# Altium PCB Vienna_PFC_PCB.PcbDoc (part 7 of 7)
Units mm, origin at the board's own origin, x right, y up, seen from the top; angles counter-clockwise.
Board outline 447.04 x 302.51 mm, 6 copper layers (Top Layer, Signal Layer 1, Signal Layer 2, Signal Layer 3, Signal Layer 4, Bottom Layer), stack 1.231 mm thick; 630 components, 255 nets, 1656 pads, 941 vias.
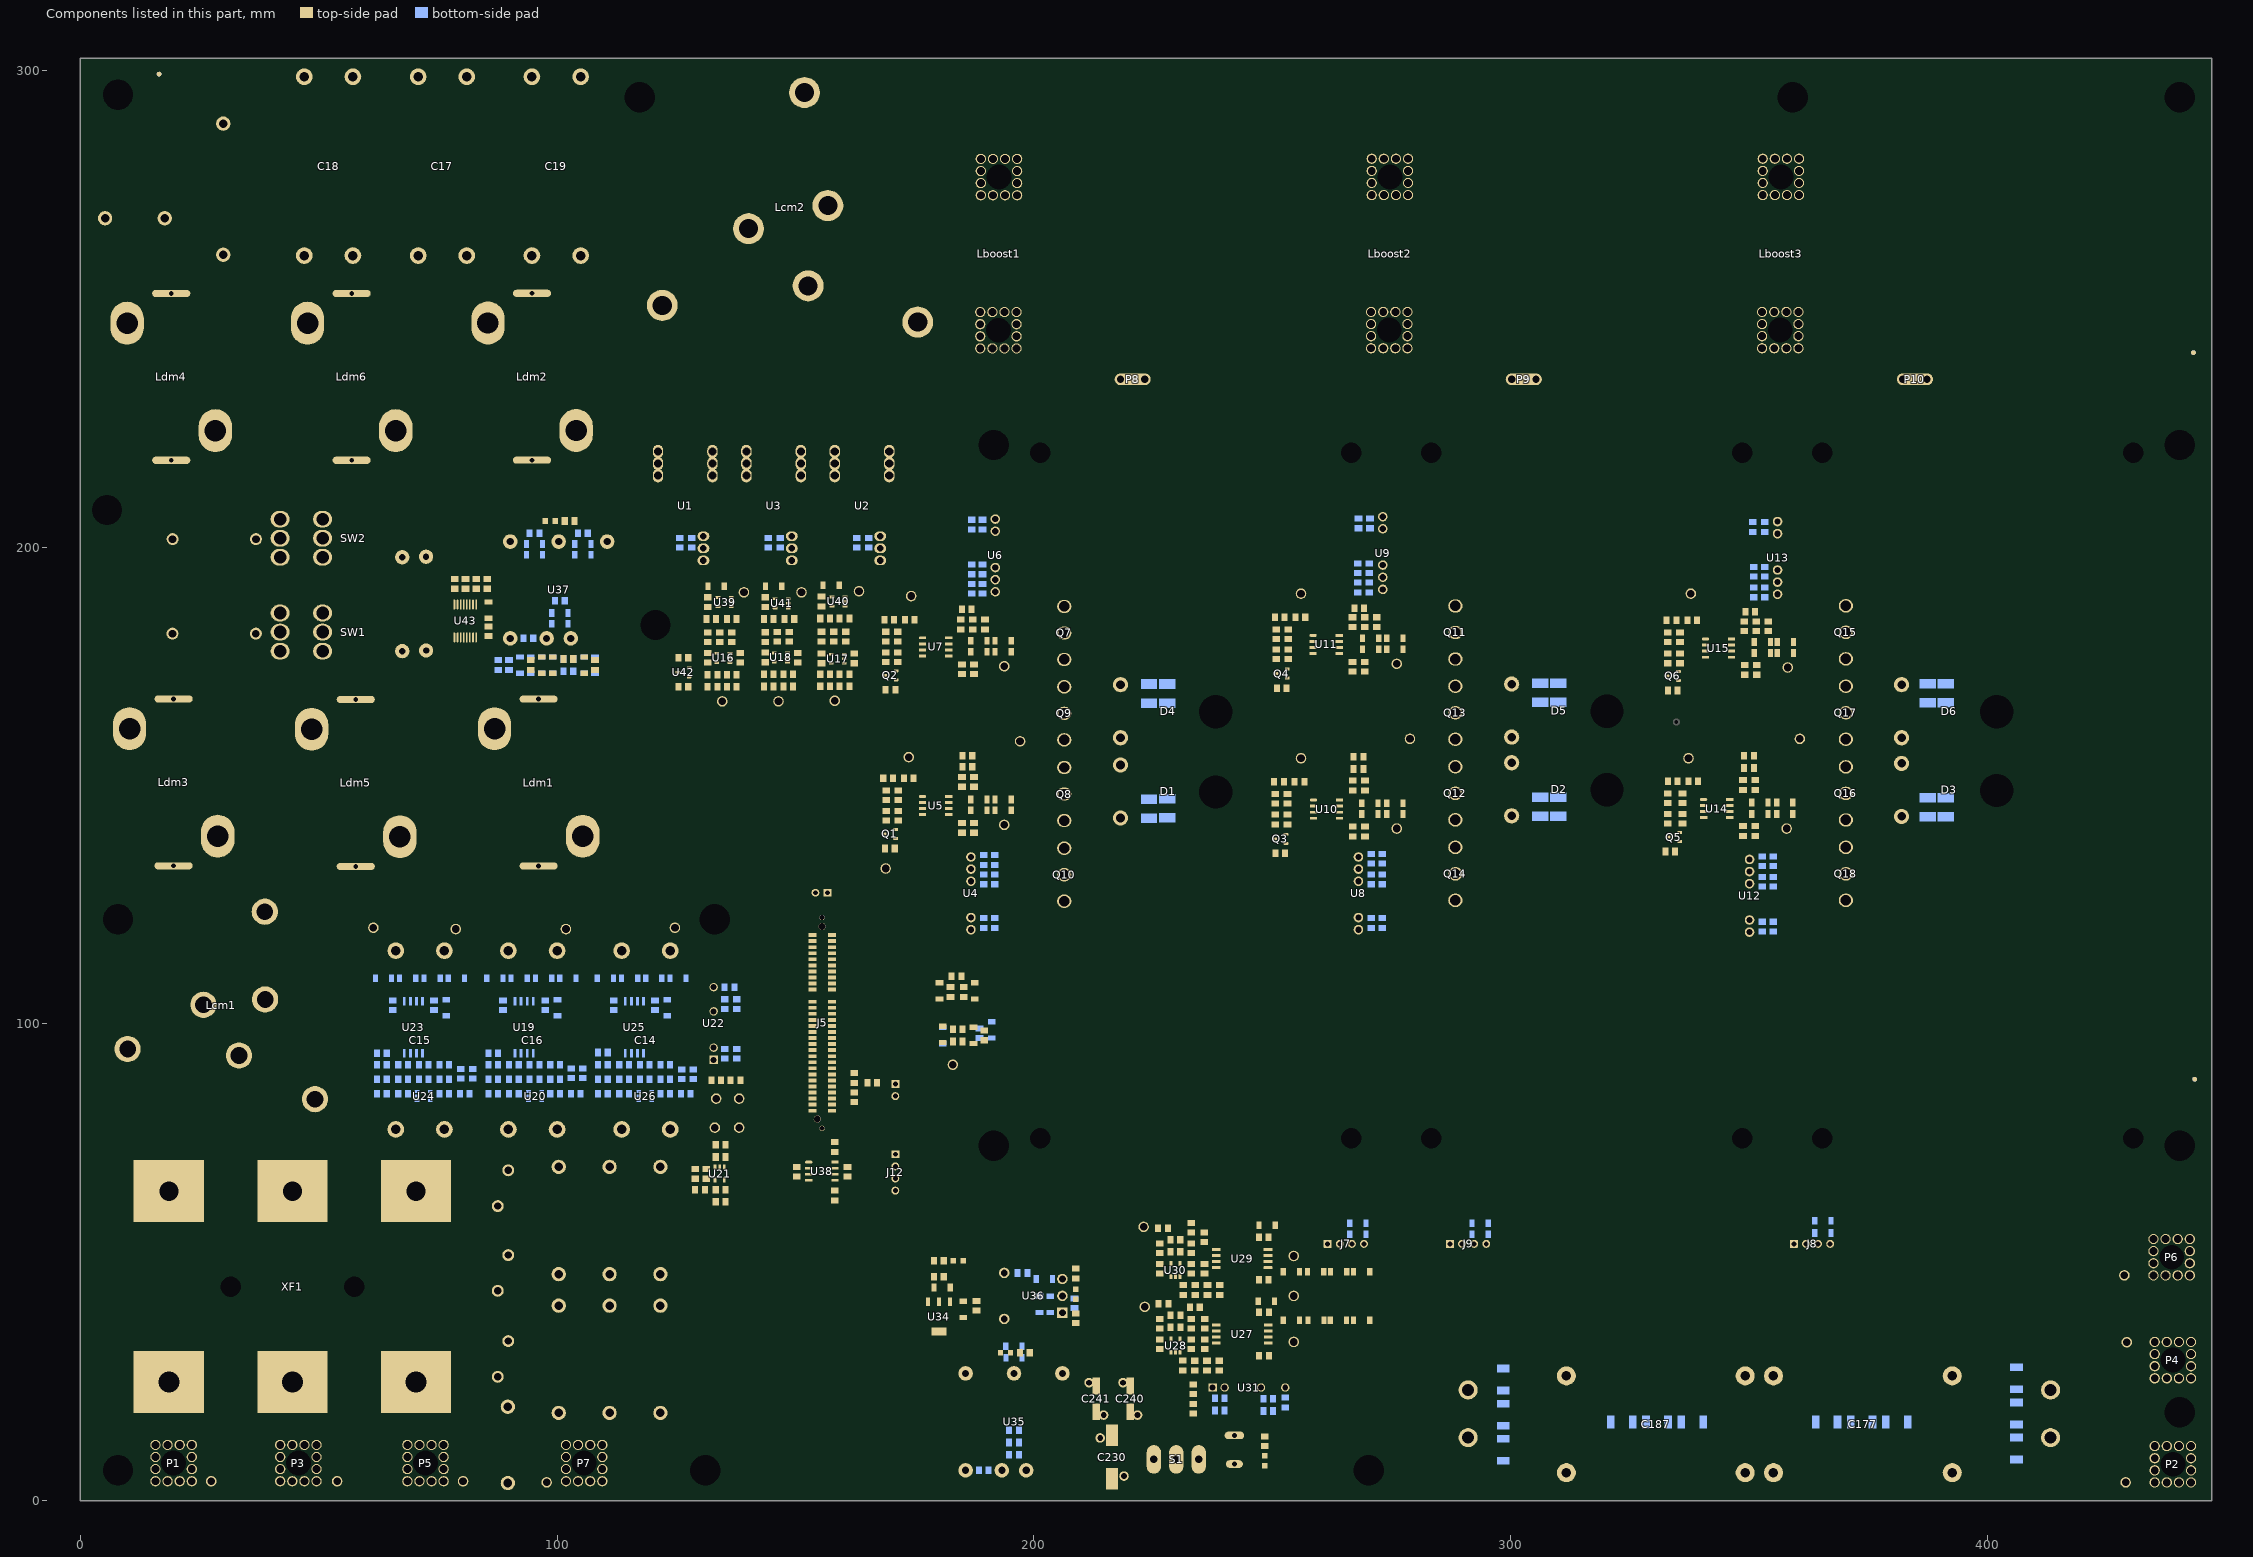
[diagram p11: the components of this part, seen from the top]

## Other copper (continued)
Signal Layer 2:
  region net V_BUS_M: 433.07,288.798 431.697,287.205 434.763,284.563 436.135,286.156
  rectangle net NetP5_1: 59.436,2.286 81.534,31.75
  rectangle net NetP3_1: 34.29,2.032 55.626,31.75
  rectangle net NetP1_1: 2.54,13.208 29.718,31.75
  rectangle net NetP1_1: 13.97,2.286 30.226,31.75
  rectangle net GND1: 197.866,165.862 199.39,169.672
  rectangle net GND1: 197.612,132.08 199.644,135.89
  rectangle net GND3: 279.908,165.608 281.94,169.418
  rectangle net GND3: 279.908,138.176 280.924,141.986
  rectangle net GND5: 361.696,166.116 363.728,169.926
  rectangle net GND5: 361.442,132.334 363.22,136.144
  pour cut-out: 370.867,55.118 ccw(c368.327,55.118) 368.327,57.658 358.14,57.658 ccw(c358.14,55.118) 355.6,55.118 355.6,52.578 ccw(c358.14,52.578) 358.14,50.038 368.327,50.038 ccw(c368.327,52.578) 370.867,52.578
  pour cut-out: 186.639,251.028 188.163,251.028 ccw(c188.163,249.504) 186.639,249.504
  pour cut-out: 186.665,212.065 187.681,212.065 cw(c187.681,213.081) 186.665,213.081
  pour cut-out: 55.143,117.881 54.127,117.881 cw(c54.127,116.865) 55.143,116.865
  pour cut-out: 2.54,34.798 3.556,34.798 cw(c3.556,35.814) 2.54,35.814
  pour cut-out: 27.94,97.561 27.94,96.545 cw(c28.956,96.545) 28.956,97.561
  pour cut-out: 36.424,97.511 35.408,97.511 cw(c35.408,96.495) 36.424,96.495
  pour cut-out: 91.68,73.538 90.664,73.538 cw(c90.664,72.522) 91.68,72.522
  pour cut-out: 29.743,108.991 28.727,108.991 cw(c28.727,107.975) 29.743,107.975
  pour cut-out: 34.214,109.296 34.214,108.28 cw(c35.23,108.28) 35.23,109.296
  pour cut-out: 368.3,299.72 369.824,299.72 ccw(c369.824,298.196) 368.3,298.196
  pour cut-out: 368.224,286.969 368.224,288.493 ccw(c369.748,288.493) 369.748,286.969
  pour cut-out: 434.264,270.459 434.264,271.983 ccw(c435.788,271.983) 435.788,270.459
  pour cut-out: 434.238,253.314 435.762,253.314 ccw(c435.762,251.79) 434.238,251.79
  pour cut-out: 425.958,235.737 427.482,235.737 ccw(c427.482,234.213) 425.958,234.213
  pour cut-out: 422.935,233.451 422.935,231.927 ccw(c421.411,231.927) 421.411,233.451
  pour cut-out: 268.935,251.079 270.459,251.079 ccw(c270.459,249.555) 268.935,249.555
  pour cut-out: 350.977,251.181 352.501,251.181 ccw(c352.501,249.657) 350.977,249.657
  pour cut-out: 198.501,251.282 198.501,249.758 ccw(c196.977,249.758) 196.977,251.282
  pour cut-out: 280.467,251.257 280.467,249.733 ccw(c278.943,249.733) 278.943,251.257
  pour cut-out: 362.509,251.257 362.509,249.733 ccw(c360.985,249.733) 360.985,251.257
  pour cut-out: 262.941,213.284 261.417,213.284 ccw(c261.417,214.808) 262.941,214.808
  pour cut-out: 268.935,213.309 268.935,214.833 ccw(c270.459,214.833) 270.459,213.309
  pour cut-out: 350.977,212.039 350.977,213.563 ccw(c352.501,213.563) 352.501,212.039
  pour cut-out: 344.5,212.039 342.976,212.039 ccw(c342.976,213.563) 344.5,213.563
  pour cut-out: 198.196,208.585 198.196,207.061 ccw(c196.672,207.061) 196.672,208.585
  pour cut-out: 280.187,208.813 280.187,207.289 ccw(c278.663,207.289) 278.663,208.813
  pour cut-out: 361.975,207.797 361.975,206.273 ccw(c360.451,206.273) 360.451,207.797
  pour cut-out: 248.361,208.839 249.885,208.839 ccw(c249.885,207.315) 248.361,207.315
  pour cut-out: 330.149,207.823 331.673,207.823 ccw(c331.673,206.299) 330.149,206.299
  pour cut-out: 198.145,202.184 196.621,202.184 ccw(c196.621,203.708) 198.145,203.708
  pour cut-out: 280.187,202.413 278.663,202.413 ccw(c278.663,203.937) 280.187,203.937
  pour cut-out: 362.001,201.397 360.477,201.397 ccw(c360.477,202.921) 362.001,202.921
  pour cut-out: 264.897,198.653 266.421,198.653 ccw(c266.421,197.129) 264.897,197.129
  pour cut-out: 346.659,197.866 348.183,197.866 ccw(c348.183,196.342) 346.659,196.342
  pour cut-out: 182.804,198.196 184.328,198.196 ccw(c184.328,196.672) 182.804,196.672
  pour cut-out: 198.171,198.171 198.171,196.647 ccw(c196.647,196.647) 196.647,198.171
  pour cut-out: 280.213,198.679 280.213,197.155 ccw(c278.689,197.155) 278.689,198.679
  pour cut-out: 362.026,197.917 362.026,196.393 ccw(c360.502,196.393) 360.502,197.917
  pour cut-out: 182.855,127.711 182.855,129.235 ccw(c184.379,129.235) 184.379,127.711
  pour cut-out: 264.922,127.508 264.922,129.032 ccw(c266.446,129.032) 266.446,127.508
  pour cut-out: 346.659,126.695 346.659,128.219 ccw(c348.183,128.219) 348.183,126.695
  pour cut-out: 201.905,191.745 201.905,193.269 ccw(c203.429,193.269) 203.429,191.745
  pour cut-out: 285.674,191.694 285.674,193.218 ccw(c287.198,193.218) 287.198,191.694
  pour cut-out: 365.735,194.285 365.735,195.809 ccw(c367.259,195.809) 367.259,194.285
  pour cut-out: 243.891,177.749 242.367,177.749 ccw(c242.367,179.273) 243.891,179.273
  pour cut-out: 326.39,178.791 324.866,178.791 ccw(c324.866,180.315) 326.39,180.315
  pour cut-out: 422.91,178.562 421.386,178.562 ccw(c421.386,180.086) 422.91,180.086
  pour cut-out: 215.875,175.311 217.399,175.311 ccw(c217.399,173.787) 215.875,173.787
  pour cut-out: 245.308,175.458 245.308,173.934 ccw(c243.784,173.934) 243.784,175.458
  pour cut-out: 298.933,175.311 300.457,175.311 ccw(c300.457,173.787) 298.933,173.787
  pour cut-out: 327.685,175.285 327.685,173.761 ccw(c326.161,173.761) 326.161,175.285
  pour cut-out: 379.959,175.285 381.483,175.285 ccw(c381.483,173.761) 379.959,173.761
  pour cut-out: 421.492,175.408 421.492,173.884 ccw(c419.968,173.884) 419.968,175.408
  pour cut-out: 444.525,83.769 443.001,83.769 ccw(c443.001,85.293) 444.525,85.293
  pour cut-out: 274.295,47.015 275.819,47.015 ccw(c275.819,45.491) 274.295,45.491
  pour cut-out: 205.207,66.269 205.207,67.793 ccw(c206.731,67.793) 206.731,66.269
  pour cut-out: 198.12,124.206 cw(c198.12,119.888) 202.438,119.888 202.438,124.206
  pour cut-out: 275.844,124.46 cw(c275.844,120.142) 280.162,120.142 280.162,124.46
  pour cut-out: 357.632,123.444 cw(c357.632,119.126) 361.95,119.126 361.95,123.444
Signal Layer 3:
  region net V_BUS_M: 433.07,288.798 431.697,287.205 434.763,284.563 436.135,286.156
  rectangle net NetP5_1: 59.436,2.286 81.534,31.75
  rectangle net NetP3_1: 34.29,2.032 55.626,31.75
  rectangle net NetP1_1: 2.54,13.208 28.702,31.75
  rectangle net NetP1_1: 13.97,2.286 29.21,31.75
  rectangle net V_N_MEAS: 60.452,103.124 61.214,120.142
  rectangle net GND1: 197.866,165.862 199.644,169.672
  rectangle net GND1: 197.612,132.08 199.136,135.89
  rectangle net GND3: 279.654,165.608 281.686,169.418
  rectangle net GND3: 279.654,138.176 281.686,141.986
  rectangle net GND5: 361.188,166.116 363.728,169.926
  rectangle net GND5: 361.696,132.334 363.22,136.144
  pour cut-out: 370.867,55.118 ccw(c368.327,55.118) 368.327,57.658 358.14,57.658 ccw(c358.14,55.118) 355.6,55.118 355.6,52.578 ccw(c358.14,52.578) 358.14,50.038 368.327,50.038 ccw(c368.327,52.578) 370.867,52.578
  pour cut-out: 186.639,251.028 188.163,251.028 ccw(c188.163,249.504) 186.639,249.504
  pour cut-out: 186.665,212.065 187.681,212.065 cw(c187.681,213.081) 186.665,213.081
  pour cut-out: 55.143,117.881 54.127,117.881 cw(c54.127,116.865) 55.143,116.865
  pour cut-out: 2.54,34.798 3.556,34.798 cw(c3.556,35.814) 2.54,35.814
  pour cut-out: 27.94,97.561 27.94,96.545 cw(c28.956,96.545) 28.956,97.561
  pour cut-out: 36.424,97.511 35.408,97.511 cw(c35.408,96.495) 36.424,96.495
  pour cut-out: 91.68,73.538 90.664,73.538 cw(c90.664,72.522) 91.68,72.522
  pour cut-out: 29.743,108.991 28.727,108.991 cw(c28.727,107.975) 29.743,107.975
  pour cut-out: 34.214,109.296 34.214,108.28 cw(c35.23,108.28) 35.23,109.296
  pour cut-out: 368.3,299.72 369.824,299.72 ccw(c369.824,298.196) 368.3,298.196
  pour cut-out: 368.224,286.969 368.224,288.493 ccw(c369.748,288.493) 369.748,286.969
  pour cut-out: 434.264,270.459 434.264,271.983 ccw(c435.788,271.983) 435.788,270.459
  pour cut-out: 434.238,253.314 435.762,253.314 ccw(c435.762,251.79) 434.238,251.79
  pour cut-out: 425.958,235.737 427.482,235.737 ccw(c427.482,234.213) 425.958,234.213
  pour cut-out: 422.935,233.451 422.935,231.927 ccw(c421.411,231.927) 421.411,233.451
  pour cut-out: 268.935,251.079 270.459,251.079 ccw(c270.459,249.555) 268.935,249.555
  pour cut-out: 350.977,251.181 352.501,251.181 ccw(c352.501,249.657) 350.977,249.657
  pour cut-out: 198.501,251.282 198.501,249.758 ccw(c196.977,249.758) 196.977,251.282
  pour cut-out: 280.467,251.257 280.467,249.733 ccw(c278.943,249.733) 278.943,251.257
  pour cut-out: 362.509,251.257 362.509,249.733 ccw(c360.985,249.733) 360.985,251.257
  pour cut-out: 262.941,213.284 261.417,213.284 ccw(c261.417,214.808) 262.941,214.808
  pour cut-out: 268.935,213.309 268.935,214.833 ccw(c270.459,214.833) 270.459,213.309
  pour cut-out: 350.977,212.039 350.977,213.563 ccw(c352.501,213.563) 352.501,212.039
  pour cut-out: 344.5,212.039 342.976,212.039 ccw(c342.976,213.563) 344.5,213.563
  pour cut-out: 198.196,208.585 198.196,207.061 ccw(c196.672,207.061) 196.672,208.585
  pour cut-out: 280.187,208.813 280.187,207.289 ccw(c278.663,207.289) 278.663,208.813
  pour cut-out: 361.975,207.797 361.975,206.273 ccw(c360.451,206.273) 360.451,207.797
  pour cut-out: 248.361,208.839 249.885,208.839 ccw(c249.885,207.315) 248.361,207.315
  pour cut-out: 330.149,207.823 331.673,207.823 ccw(c331.673,206.299) 330.149,206.299
  pour cut-out: 198.145,202.184 196.621,202.184 ccw(c196.621,203.708) 198.145,203.708
  pour cut-out: 280.187,202.413 278.663,202.413 ccw(c278.663,203.937) 280.187,203.937
  pour cut-out: 362.001,201.397 360.477,201.397 ccw(c360.477,202.921) 362.001,202.921
  pour cut-out: 264.897,198.653 266.421,198.653 ccw(c266.421,197.129) 264.897,197.129
  pour cut-out: 346.659,197.866 348.183,197.866 ccw(c348.183,196.342) 346.659,196.342
  pour cut-out: 182.804,198.196 184.328,198.196 ccw(c184.328,196.672) 182.804,196.672
  pour cut-out: 198.171,198.171 198.171,196.647 ccw(c196.647,196.647) 196.647,198.171
  pour cut-out: 280.213,198.679 280.213,197.155 ccw(c278.689,197.155) 278.689,198.679
  pour cut-out: 362.026,197.917 362.026,196.393 ccw(c360.502,196.393) 360.502,197.917
  pour cut-out: 182.855,127.711 182.855,129.235 ccw(c184.379,129.235) 184.379,127.711
  pour cut-out: 264.922,127.508 264.922,129.032 ccw(c266.446,129.032) 266.446,127.508
  pour cut-out: 346.659,126.695 346.659,128.219 ccw(c348.183,128.219) 348.183,126.695
  pour cut-out: 201.905,191.745 201.905,193.269 ccw(c203.429,193.269) 203.429,191.745
  pour cut-out: 285.674,191.694 285.674,193.218 ccw(c287.198,193.218) 287.198,191.694
  pour cut-out: 365.735,194.285 365.735,195.809 ccw(c367.259,195.809) 367.259,194.285
  pour cut-out: 243.891,177.749 242.367,177.749 ccw(c242.367,179.273) 243.891,179.273
  pour cut-out: 326.39,178.791 324.866,178.791 ccw(c324.866,180.315) 326.39,180.315
  pour cut-out: 422.91,178.562 421.386,178.562 ccw(c421.386,180.086) 422.91,180.086
  pour cut-out: 215.875,175.311 217.399,175.311 ccw(c217.399,173.787) 215.875,173.787
  pour cut-out: 245.308,175.458 245.308,173.934 ccw(c243.784,173.934) 243.784,175.458
  pour cut-out: 298.933,175.311 300.457,175.311 ccw(c300.457,173.787) 298.933,173.787
  pour cut-out: 327.685,175.285 327.685,173.761 ccw(c326.161,173.761) 326.161,175.285
  pour cut-out: 379.959,175.285 381.483,175.285 ccw(c381.483,173.761) 379.959,173.761
  pour cut-out: 421.492,175.408 421.492,173.884 ccw(c419.968,173.884) 419.968,175.408
  pour cut-out: 444.525,83.769 443.001,83.769 ccw(c443.001,85.293) 444.525,85.293
  pour cut-out: 274.295,47.015 275.819,47.015 ccw(c275.819,45.491) 274.295,45.491
  pour cut-out: 205.207,66.269 205.207,67.793 ccw(c206.731,67.793) 206.731,66.269
  pour cut-out: 198.12,124.206 cw(c198.12,119.888) 202.438,119.888 202.438,124.206
  pour cut-out: 275.844,124.46 cw(c275.844,120.142) 280.162,120.142 280.162,124.46
  pour cut-out: 357.632,123.444 cw(c357.632,119.126) 361.95,119.126 361.95,123.444
Signal Layer 4:
  region net V_BUS_M: 432.919,288.867 431.546,287.274 434.611,284.632 435.984,286.225
  rectangle net VBUSP: 423.672,2.032 444.5,12.954
  rectangle net NetP5_1: 59.436,2.286 81.534,31.75
  rectangle net NetP3_1: 33.02,2.032 56.134,31.75
  rectangle net NetP1_1: 2.54,13.208 29.464,31.75
  rectangle net NetP1_1: 13.97,2.286 29.464,31.75
  rectangle net GND1: 197.866,165.862 199.136,169.672
  rectangle net GND1: 197.866,131.868 198.628,135.89
  rectangle net GND3: 279.908,165.608 280.924,169.418
  rectangle net GND3: 279.908,138.176 280.924,141.986
  rectangle net GND5: 361.442,166.116 362.712,169.926
  rectangle net GND5: 361.696,132.334 362.712,136.144
  rectangle net NetC8_2: 31.242,114.808 36.322,118.11
  pour cut-out: 370.867,55.118 ccw(c368.327,55.118) 368.327,57.658 358.14,57.658 ccw(c358.14,55.118) 355.6,55.118 355.6,52.578 ccw(c358.14,52.578) 358.14,50.038 368.327,50.038 ccw(c368.327,52.578) 370.867,52.578
  pour cut-out: 186.639,251.028 188.163,251.028 ccw(c188.163,249.504) 186.639,249.504
  pour cut-out: 123.698,64.77 122.682,64.77 cw(c122.682,63.754) 123.698,63.754
  pour cut-out: 98.298,64.77 98.298,63.754 cw(c99.314,63.754) 99.314,64.77
  pour cut-out: 186.665,212.065 187.681,212.065 cw(c187.681,213.081) 186.665,213.081
  pour cut-out: 55.143,117.881 54.127,117.881 cw(c54.127,116.865) 55.143,116.865
  pour cut-out: 2.54,34.798 3.556,34.798 cw(c3.556,35.814) 2.54,35.814
  pour cut-out: 27.94,97.561 27.94,96.545 cw(c28.956,96.545) 28.956,97.561
  pour cut-out: 36.424,97.511 35.408,97.511 cw(c35.408,96.495) 36.424,96.495
  pour cut-out: 91.68,73.538 90.664,73.538 cw(c90.664,72.522) 91.68,72.522
  pour cut-out: 29.743,108.991 28.727,108.991 cw(c28.727,107.975) 29.743,107.975
  pour cut-out: 34.214,109.296 34.214,108.28 cw(c35.23,108.28) 35.23,109.296
  pour cut-out: 368.3,299.72 369.824,299.72 ccw(c369.824,298.196) 368.3,298.196
  pour cut-out: 368.224,286.969 368.224,288.493 ccw(c369.748,288.493) 369.748,286.969
  pour cut-out: 434.264,270.459 434.264,271.983 ccw(c435.788,271.983) 435.788,270.459
  pour cut-out: 434.238,253.314 435.762,253.314 ccw(c435.762,251.79) 434.238,251.79
  pour cut-out: 425.958,235.737 427.482,235.737 ccw(c427.482,234.213) 425.958,234.213
  pour cut-out: 422.935,233.451 422.935,231.927 ccw(c421.411,231.927) 421.411,233.451
  pour cut-out: 268.935,251.079 270.459,251.079 ccw(c270.459,249.555) 268.935,249.555
  pour cut-out: 350.977,251.181 352.501,251.181 ccw(c352.501,249.657) 350.977,249.657
  pour cut-out: 198.501,251.282 198.501,249.758 ccw(c196.977,249.758) 196.977,251.282
  pour cut-out: 280.467,251.257 280.467,249.733 ccw(c278.943,249.733) 278.943,251.257
  pour cut-out: 362.509,251.257 362.509,249.733 ccw(c360.985,249.733) 360.985,251.257
  pour cut-out: 262.941,213.284 261.417,213.284 ccw(c261.417,214.808) 262.941,214.808
  pour cut-out: 268.935,213.309 268.935,214.833 ccw(c270.459,214.833) 270.459,213.309
  pour cut-out: 350.977,212.039 350.977,213.563 ccw(c352.501,213.563) 352.501,212.039
  pour cut-out: 344.5,212.039 342.976,212.039 ccw(c342.976,213.563) 344.5,213.563
  pour cut-out: 198.196,208.585 198.196,207.061 ccw(c196.672,207.061) 196.672,208.585
  pour cut-out: 280.187,208.813 280.187,207.289 ccw(c278.663,207.289) 278.663,208.813
  pour cut-out: 361.975,207.797 361.975,206.273 ccw(c360.451,206.273) 360.451,207.797
  pour cut-out: 248.361,208.839 249.885,208.839 ccw(c249.885,207.315) 248.361,207.315
  pour cut-out: 330.149,207.823 331.673,207.823 ccw(c331.673,206.299) 330.149,206.299
  pour cut-out: 198.145,202.184 196.621,202.184 ccw(c196.621,203.708) 198.145,203.708
  pour cut-out: 280.187,202.413 278.663,202.413 ccw(c278.663,203.937) 280.187,203.937
  pour cut-out: 362.001,201.397 360.477,201.397 ccw(c360.477,202.921) 362.001,202.921
  pour cut-out: 264.897,198.653 266.421,198.653 ccw(c266.421,197.129) 264.897,197.129
  pour cut-out: 346.659,197.866 348.183,197.866 ccw(c348.183,196.342) 346.659,196.342
  pour cut-out: 182.804,198.196 184.328,198.196 ccw(c184.328,196.672) 182.804,196.672
  pour cut-out: 198.171,198.171 198.171,196.647 ccw(c196.647,196.647) 196.647,198.171
  pour cut-out: 280.213,198.679 280.213,197.155 ccw(c278.689,197.155) 278.689,198.679
  pour cut-out: 362.026,197.917 362.026,196.393 ccw(c360.502,196.393) 360.502,197.917
  pour cut-out: 182.855,127.711 182.855,129.235 ccw(c184.379,129.235) 184.379,127.711
  pour cut-out: 264.922,127.508 264.922,129.032 ccw(c266.446,129.032) 266.446,127.508
  pour cut-out: 346.659,126.695 346.659,128.219 ccw(c348.183,128.219) 348.183,126.695
  pour cut-out: 201.905,191.745 201.905,193.269 ccw(c203.429,193.269) 203.429,191.745
  pour cut-out: 285.674,191.694 285.674,193.218 ccw(c287.198,193.218) 287.198,191.694
  pour cut-out: 365.735,194.285 365.735,195.809 ccw(c367.259,195.809) 367.259,194.285
  pour cut-out: 243.891,177.749 242.367,177.749 ccw(c242.367,179.273) 243.891,179.273
  pour cut-out: 326.39,178.791 324.866,178.791 ccw(c324.866,180.315) 326.39,180.315
  pour cut-out: 422.91,178.562 421.386,178.562 ccw(c421.386,180.086) 422.91,180.086
  pour cut-out: 215.875,175.311 217.399,175.311 ccw(c217.399,173.787) 215.875,173.787
  pour cut-out: 245.308,175.458 245.308,173.934 ccw(c243.784,173.934) 243.784,175.458
  pour cut-out: 298.933,175.311 300.457,175.311 ccw(c300.457,173.787) 298.933,173.787
  pour cut-out: 327.685,175.285 327.685,173.761 ccw(c326.161,173.761) 326.161,175.285
  pour cut-out: 379.959,175.285 381.483,175.285 ccw(c381.483,173.761) 379.959,173.761
  pour cut-out: 421.492,175.408 421.492,173.884 ccw(c419.968,173.884) 419.968,175.408
  pour cut-out: 444.525,83.769 443.001,83.769 ccw(c443.001,85.293) 444.525,85.293
  pour cut-out: 274.295,47.015 275.819,47.015 ccw(c275.819,45.491) 274.295,45.491
  pour cut-out: 205.207,66.269 205.207,67.793 ccw(c206.731,67.793) 206.731,66.269
  pour cut-out: 198.12,124.206 cw(c198.12,119.888) 202.438,119.888 202.438,124.206
  pour cut-out: 275.844,124.46 cw(c275.844,120.142) 280.162,120.142 280.162,124.46
  pour cut-out: 357.632,123.444 cw(c357.632,119.126) 361.95,119.126 361.95,123.444
Bottom Layer:
  region net V_BUS_M: 433.07,288.798 431.697,287.205 434.763,284.563 436.135,286.156
  rectangle net -5V6: 348.996,127.889 356.146,129.54
  rectangle net +20V6: 348.996,134.366 356.146,136.017
  rectangle net +20V5: 349.974,188.595 357.124,190.246
  rectangle net -5V5: 349.974,195.326 357.124,196.723
  rectangle net DGND: 350.012,201.93 356.87,203.708
  rectangle net +12V_D: 350.012,204.724 356.87,206.248
  rectangle net -5V4: 267.462,128.397 274.104,130.048
  rectangle net +20V4: 267.208,134.62 274.574,136.906
  rectangle net +20V3: 266.7,189.484 274.066,191.262
  rectangle net -5V3: 266.954,195.834 274.066,197.612
  rectangle net +20V1: 185.928,188.722 192.786,190.754
  rectangle net -5V1: 185.674,195.834 193.04,197.358
  rectangle net -5V2: 185.687,128.245 192.532,129.794
  rectangle net +20V2: 185.674,134.874 192.786,136.398
  rectangle net +12V_D: 267.208,118.872 273.812,120.904
  rectangle net DGND: 267.208,121.412 273.812,123.19
  rectangle net DGND: 267.208,202.692 274.32,204.724
  rectangle net +12V_D: 267.208,205.486 274.32,208.28
  rectangle net +12V_D: 185.674,118.872 192.532,120.65
  rectangle net DGND: 185.674,121.666 192.532,123.444
  rectangle net +12V_D: 186.182,205.232 193.04,207.01
  rectangle net DGND: 186.182,202.438 192.786,204.216
  rectangle net VBUSN: 421.64,45.72 444.246,66.802
  rectangle net V_BUS_M: 349.25,4.064 355.346,27.94
  rectangle net VBUSP: 413.512,7.366 444.5,12.954
  rectangle net V_BUS_M: 356.362,12.7 364.49,20.32
  rectangle net NetR134_1: 368.046,12.7 371.856,20.32
  rectangle net NetR132_1: 375.412,12.7 379.222,20.32
  rectangle net VBUSP: 382.778,12.7 390.906,20.32
  rectangle net V_BUS_M: 339.852,12.7 347.98,20.32
  rectangle net NetR146_1: 332.232,12.7 336.296,20.32
  rectangle net NetR148_1: 325.12,12.7 328.93,20.32
  rectangle net VBUSN: 313.436,12.7 321.603,20.32
  rectangle net NetR133_1: 403.352,12.446 407.67,16.764
  rectangle net NetR135_1: 403.352,20.066 407.67,23.876
  region net V_BUS_M: 417.322,28.702 410.972,28.702 410.972,20.574 417.322,20.574
  region net V_BUS_M: 444.246,35.052 403.352,35.052 403.352,27.686 444.246,27.686
  region net VBUSP: 417.322,16.002 410.972,16.002 410.972,7.874 417.322,7.874
  region net VBUSP: 444.5,9.144 390.652,9.144 390.652,2.032 444.5,2.032
  rectangle net NetR149_1: 297.18,12.192 301.244,16.51
  rectangle net NetR147_1: 296.926,20.066 301.244,23.622
  rectangle net VBUSN: 287.274,7.62 293.624,15.748
  rectangle net VBUSN: 287.274,3.556 301.244,8.89
  rectangle net V_BUS_M: 287.274,20.32 293.116,28.448
  rectangle net V_BUS_M: 287.274,27.686 301.244,32.766
  rectangle net GND_IN: 294.132,52.578 296.164,59.182
  rectangle net 12V_IN: 291.084,52.578 293.37,59.182
  rectangle net GND_IN: 268.732,52.578 270.51,59.182
  rectangle net 12V_IN: 265.43,52.578 267.462,59.182
  region net NetP5_1: 81.534,31.75 59.436,31.75 59.436,2.286 81.534,2.286
  region net NetP3_1: 56.134,31.75 33.274,31.75 33.274,2.032 56.134,2.032
  rectangle net NetP1_1: 13.97,2.286 29.21,31.75
  rectangle net NetP1_1: 2.54,13.208 29.21,31.75
  rectangle net GND: 61.976,86.36 62.992,87.376
  rectangle net GND: 61.722,94.488 62.738,95.504
  rectangle net -15V: 87.122,197.358 94.742,203.962
  rectangle net GND: 95.758,190.754 104.902,203.962
  rectangle net +15V: 105.918,197.358 113.538,203.962
  rectangle net -15V: 91.694,202.438 93.218,203.708
  rectangle net GND: 94.488,178.054 100.33,192.024
  rectangle net NetR170_1: 88.646,178.054 93.472,186.436
  rectangle net +12V: 100.838,178.054 109.855,189.992
  region net NetC211_1: 207.264,37.846 207.264,40.894 199.898,40.894 199.898,37.846
  region net GND: 207.264,41.402 207.264,44.45 195.834,44.45 195.834,41.402
  region net +5V: 207.264,44.958 207.264,49.53 203.2,49.53 203.2,44.958
  region net GND: 201.168,41.402 201.168,48.514 198.12,48.514 198.12,41.402
  region net NetR167_2: 197.104,46.228 197.104,49.276 192.278,49.276 192.278,46.228
  region net NetC211_1: 210.82,38.608 210.82,40.894 206.248,40.894 206.248,38.608
  region net GND: 209.296,41.91 209.296,42.926 206.756,42.926 206.756,41.91
  rectangle net GND_IN: 189.992,3.556 195.58,15.748
  rectangle net NetC206_1: 196.088,4.826 200.914,15.748
  rectangle net NetR168_1: 183.642,3.556 188.976,8.636
  rectangle net GND: 182.626,28.956 194.564,33.274
  rectangle net GND: 182.626,19.05 192.532,33.274
  rectangle net +12V: 197.104,28.956 209.042,33.274
  rectangle net +12V: 198.882,19.05 209.042,33.274
  rectangle net +3.3V: 87.122,89.916 88.138,90.932
  rectangle net GND: 85.598,86.36 86.614,87.376
  rectangle net GND: 85.09,94.488 86.106,95.504
  rectangle net GND: 100.076,83.566 101.092,84.582
  rectangle net +3.3V: 97.094,83.566 98.552,84.582
  rectangle net GND: 104.902,91.186 105.918,92.202
  rectangle net GND: 81.788,91.186 82.804,92.202
  rectangle net GND: 128.016,90.932 129.032,91.948
  rectangle net +3.3V: 63.754,89.916 64.77,90.932
  rectangle net GND: 108.458,86.36 109.474,87.376
  rectangle net GND: 107.95,94.488 108.966,95.504
  rectangle net +3.3V: 73.853,83.566 75.692,84.582
  rectangle net +3.3V: 120.208,83.566 121.92,84.582
  rectangle net GND: 76.708,83.566 77.724,84.582
  rectangle net GND: 123.063,83.566 124.079,84.582
  rectangle net GND: 117.856,92.964 119.634,94.742
  rectangle net GND: 118.618,93.218 119.634,94.234
  rectangle net GND: 71.628,92.964 73.66,94.742
  rectangle net GND: 72.644,93.218 73.66,94.234
  rectangle net GND: 94.742,92.964 97.028,94.742
  rectangle net GND: 95.25,93.218 96.266,94.234
  rectangle net V_BUS_M: 246.38,18.034 248.666,24.892
  rectangle net 5V_M: 249.682,18.034 250.952,22.098
  rectangle net 5V_M: 250.444,18.034 253.492,20.066
  rectangle net NetL7_1: 251.968,21.082 253.746,24.892
  rectangle net GND3: 278.892,165.608 281.686,169.418
  rectangle net GND3: 279.4,138.176 282.194,141.986
  rectangle net GND1: 196.85,165.862 199.644,169.672
  rectangle net GND1: 196.85,132.08 199.644,135.89
  rectangle net GND5: 360.426,166.116 363.22,169.926
  rectangle net GND5: 360.68,132.334 363.474,136.144
  rectangle net GND: 70.358,84.582 71.882,85.09
  rectangle net GND: 93.726,84.582 95.25,85.09
  rectangle net GND: 116.84,84.582 118.364,85.09
  rectangle net +3.3V: 109.982,89.662 111.252,94.742
  rectangle net V_N_MEAS: 61.214,101.346 77.47,103.378
  rectangle net V_N_MEAS: 87.884,101.346 100.838,103.378
  rectangle net V_N_MEAS: 110.998,101.346 123.952,103.378
  rectangle net 5V_N: 64.77,104.14 68.072,105.664
  rectangle net 5V_N: 87.884,104.14 91.44,105.664
  rectangle net 5V_N: 110.998,104.14 114.554,105.918
  rectangle net V_N_MEAS: 71.374,102.87 72.136,105.664
  rectangle net V_N_MEAS: 94.742,103.124 95.25,105.664
  rectangle net V_N_MEAS: 117.856,102.87 118.364,105.664
  rectangle net NetC141_1: 73.406,104.394 77.47,105.41
  rectangle net NetC126_1: 96.774,104.394 100.838,105.41
  rectangle net NetC151_1: 119.634,104.394 123.952,105.41
  rectangle net NetL5_1: 131.826,106.934 135.636,108.458
  rectangle net 5V_N: 136.906,104.394 138.684,108.712
  rectangle net 5V_N: 131.572,104.394 138.684,105.918
  rectangle net GND: 131.572,94.234 138.43,96.52
  rectangle net NetC227_1: 131.572,91.44 138.43,93.472
  rectangle net REF_1V65: 64.77,84.582 67.31,86.106
  rectangle net REF_1V65: 87.122,84.582 90.424,86.106
  rectangle net REF_1V65: 109.982,84.582 113.538,86.106
  rectangle net NetC122_2: 104.648,84.328 106.426,89.408
  rectangle net NetC139_2: 81.28,84.582 83.312,89.154
  rectangle net NetC206_1: 211.328,11.43 221.488,16.002
  rectangle net GND_IN: 211.074,2.286 221.742,7.62
  rectangle net 5V_M: 249.428,18.034 250.952,24.892
  rectangle net GND: 177.292,93.218 183.261,97.961
  rectangle net GND: 178.435,93.218 183.261,95.25
  rectangle net DGND: 184.15,90.17 192.151,95.25
  rectangle net DGND: 187.579,93.726 192.151,97.847
  rectangle net DGND: 348.996,120.904 355.854,122.682
  rectangle net +12V: 103.124,175.514 108.712,179.705
  rectangle net GND: 102.87,172.212 114.3,174.498
  rectangle net +12V: 177.292,98.298 183.388,102.362
  rectangle net DGND2: 86.614,171.45 101.854,174.498
  pour cut-out: 368.327,50.038 ccw(c368.327,52.578) 370.867,52.578 370.867,59.944 ccw(c368.186,59.804) 368.046,62.484 358.14,62.484 ccw(c358.14,59.944) 355.6,59.944 355.6,52.578 ccw(c358.14,52.578) 358.14,50.038
  pour cut-out: 186.639,251.028 188.163,251.028 ccw(c188.163,249.504) 186.639,249.504
  pour cut-out: 186.665,212.065 187.681,212.065 cw(c187.681,213.081) 186.665,213.081
  pour cut-out: 55.143,117.881 54.127,117.881 cw(c54.127,116.865) 55.143,116.865
  pour cut-out: 2.54,34.798 3.556,34.798 cw(c3.556,35.814) 2.54,35.814
  pour cut-out: 27.94,97.561 27.94,96.545 cw(c28.956,96.545) 28.956,97.561
  pour cut-out: 36.424,97.511 35.408,97.511 cw(c35.408,96.495) 36.424,96.495
  pour cut-out: 91.68,73.538 90.664,73.538 cw(c90.664,72.522) 91.68,72.522
  pour cut-out: 29.743,108.991 28.727,108.991 cw(c28.727,107.975) 29.743,107.975
  pour cut-out: 34.214,109.296 34.214,108.28 cw(c35.23,108.28) 35.23,109.296
  pour cut-out: 368.3,299.72 369.824,299.72 ccw(c369.824,298.196) 368.3,298.196
  pour cut-out: 368.224,286.969 368.224,288.493 ccw(c369.748,288.493) 369.748,286.969
  pour cut-out: 434.264,270.459 434.264,271.983 ccw(c435.788,271.983) 435.788,270.459
  pour cut-out: 434.238,253.314 435.762,253.314 ccw(c435.762,251.79) 434.238,251.79
  pour cut-out: 425.958,235.737 427.482,235.737 ccw(c427.482,234.213) 425.958,234.213
  pour cut-out: 422.935,233.451 422.935,231.927 ccw(c421.411,231.927) 421.411,233.451
  pour cut-out: 268.935,251.079 270.459,251.079 ccw(c270.459,249.555) 268.935,249.555
  pour cut-out: 350.977,251.181 352.501,251.181 ccw(c352.501,249.657) 350.977,249.657
  pour cut-out: 198.501,251.282 198.501,249.758 ccw(c196.977,249.758) 196.977,251.282
  pour cut-out: 280.467,251.257 280.467,249.733 ccw(c278.943,249.733) 278.943,251.257
  pour cut-out: 362.509,251.257 362.509,249.733 ccw(c360.985,249.733) 360.985,251.257
  pour cut-out: 262.941,213.284 261.417,213.284 ccw(c261.417,214.808) 262.941,214.808
  pour cut-out: 268.935,213.309 268.935,214.833 ccw(c270.459,214.833) 270.459,213.309
  pour cut-out: 350.977,212.039 350.977,213.563 ccw(c352.501,213.563) 352.501,212.039
  pour cut-out: 344.5,212.039 342.976,212.039 ccw(c342.976,213.563) 344.5,213.563
  pour cut-out: 198.196,208.585 198.196,207.061 ccw(c196.672,207.061) 196.672,208.585
  pour cut-out: 280.187,208.813 280.187,207.289 ccw(c278.663,207.289) 278.663,208.813
  pour cut-out: 361.975,207.797 361.975,206.273 ccw(c360.451,206.273) 360.451,207.797
  pour cut-out: 248.361,208.839 249.885,208.839 ccw(c249.885,207.315) 248.361,207.315
  pour cut-out: 330.149,207.823 331.673,207.823 ccw(c331.673,206.299) 330.149,206.299
  pour cut-out: 198.145,202.184 196.621,202.184 ccw(c196.621,203.708) 198.145,203.708
  pour cut-out: 280.187,202.413 278.663,202.413 ccw(c278.663,203.937) 280.187,203.937
  pour cut-out: 362.001,201.397 360.477,201.397 ccw(c360.477,202.921) 362.001,202.921
  pour cut-out: 264.897,198.653 266.421,198.653 ccw(c266.421,197.129) 264.897,197.129
  pour cut-out: 346.659,197.866 348.183,197.866 ccw(c348.183,196.342) 346.659,196.342
  pour cut-out: 182.804,198.196 184.328,198.196 ccw(c184.328,196.672) 182.804,196.672
  pour cut-out: 198.171,198.171 198.171,196.647 ccw(c196.647,196.647) 196.647,198.171
  pour cut-out: 280.213,198.679 280.213,197.155 ccw(c278.689,197.155) 278.689,198.679
  pour cut-out: 362.026,197.917 362.026,196.393 ccw(c360.502,196.393) 360.502,197.917
  pour cut-out: 182.855,127.711 182.855,129.235 ccw(c184.379,129.235) 184.379,127.711
  pour cut-out: 264.922,127.508 264.922,129.032 ccw(c266.446,129.032) 266.446,127.508
  pour cut-out: 346.659,126.695 346.659,128.219 ccw(c348.183,128.219) 348.183,126.695
  pour cut-out: 201.905,191.745 201.905,193.269 ccw(c203.429,193.269) 203.429,191.745
  pour cut-out: 285.674,191.694 285.674,193.218 ccw(c287.198,193.218) 287.198,191.694
  pour cut-out: 365.735,194.285 365.735,195.809 ccw(c367.259,195.809) 367.259,194.285
  pour cut-out: 243.891,177.749 242.367,177.749 ccw(c242.367,179.273) 243.891,179.273
  pour cut-out: 326.39,178.791 324.866,178.791 ccw(c324.866,180.315) 326.39,180.315
  pour cut-out: 422.91,178.562 421.386,178.562 ccw(c421.386,180.086) 422.91,180.086
  pour cut-out: 215.875,175.311 217.399,175.311 ccw(c217.399,173.787) 215.875,173.787
  pour cut-out: 245.308,175.458 245.308,173.934 ccw(c243.784,173.934) 243.784,175.458
  pour cut-out: 298.933,175.311 300.457,175.311 ccw(c300.457,173.787) 298.933,173.787
  pour cut-out: 327.685,175.285 327.685,173.761 ccw(c326.161,173.761) 326.161,175.285
  pour cut-out: 379.959,175.285 381.483,175.285 ccw(c381.483,173.761) 379.959,173.761
  pour cut-out: 421.492,175.408 421.492,173.884 ccw(c419.968,173.884) 419.968,175.408
  pour cut-out: 444.525,83.769 443.001,83.769 ccw(c443.001,85.293) 444.525,85.293
  pour cut-out: 274.295,47.015 275.819,47.015 ccw(c275.819,45.491) 274.295,45.491
  pour cut-out: 205.207,66.269 205.207,67.793 ccw(c206.731,67.793) 206.731,66.269
  pour cut-out: 198.12,124.206 cw(c198.12,119.888) 202.438,119.888 202.438,124.206
  pour cut-out: 275.844,124.46 cw(c275.844,120.142) 280.162,120.142 280.162,124.46
  pour cut-out: 357.632,123.444 cw(c357.632,119.126) 361.95,119.126 361.95,123.444

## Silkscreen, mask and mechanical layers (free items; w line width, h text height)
Top Overlay:
  drawing of 1891 lines, arcs and shapes, not listed
  text "Microsemi" at 370.078,50.546 h6.35
  text "Version 1.2" at 370.586,46.482 h2.79
  text "MARCH, 2019" at 384.302,46.482 h2.54
  text "By Dakai Wang" at 400.05,46.482 h2.54
  text "VBUS_N" at 446.532,45.466 h1.52 r90
  text "VBUS_M" at 446.786,23.876 h1.52 r90
  text "VBUS_P" at 446.786,2.286 h1.52 r90
  text "Phase_1" at 18.923,0.508 h1.27
  text "Phase_2" at 45.466,0.508 h1.27
  text "Phase_3" at 72.136,0.508 h1.27
  text "PE" at 108.585,0.381 h1.52
  text "Input / 12V DC / 1Amps" at 245.872,-0.762 h1.8
Mechanical 1:
  lines w0.1: 200.928,255.996 191.911,255.996 191.911,267.045 200.928,267.045 ; 266.993,257.012 282.894,257.012 ; 266.993,266.016 282.919,266.016 ; 349.01,257.025 364.91,257.025 ; 349.01,266.016 364.91,266.016 ; 431.001,255.996 440.018,255.996 440.018,267.045 431.001,267.045
  lines w0.127: 0,0 0,302.514 447.04,302.514 447.04,0 0,0
Mechanical 5:
  drawing of 279 lines, arcs and shapes, not listed
Mechanical 13:
  drawing of 5263 lines, arcs and shapes, not listed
